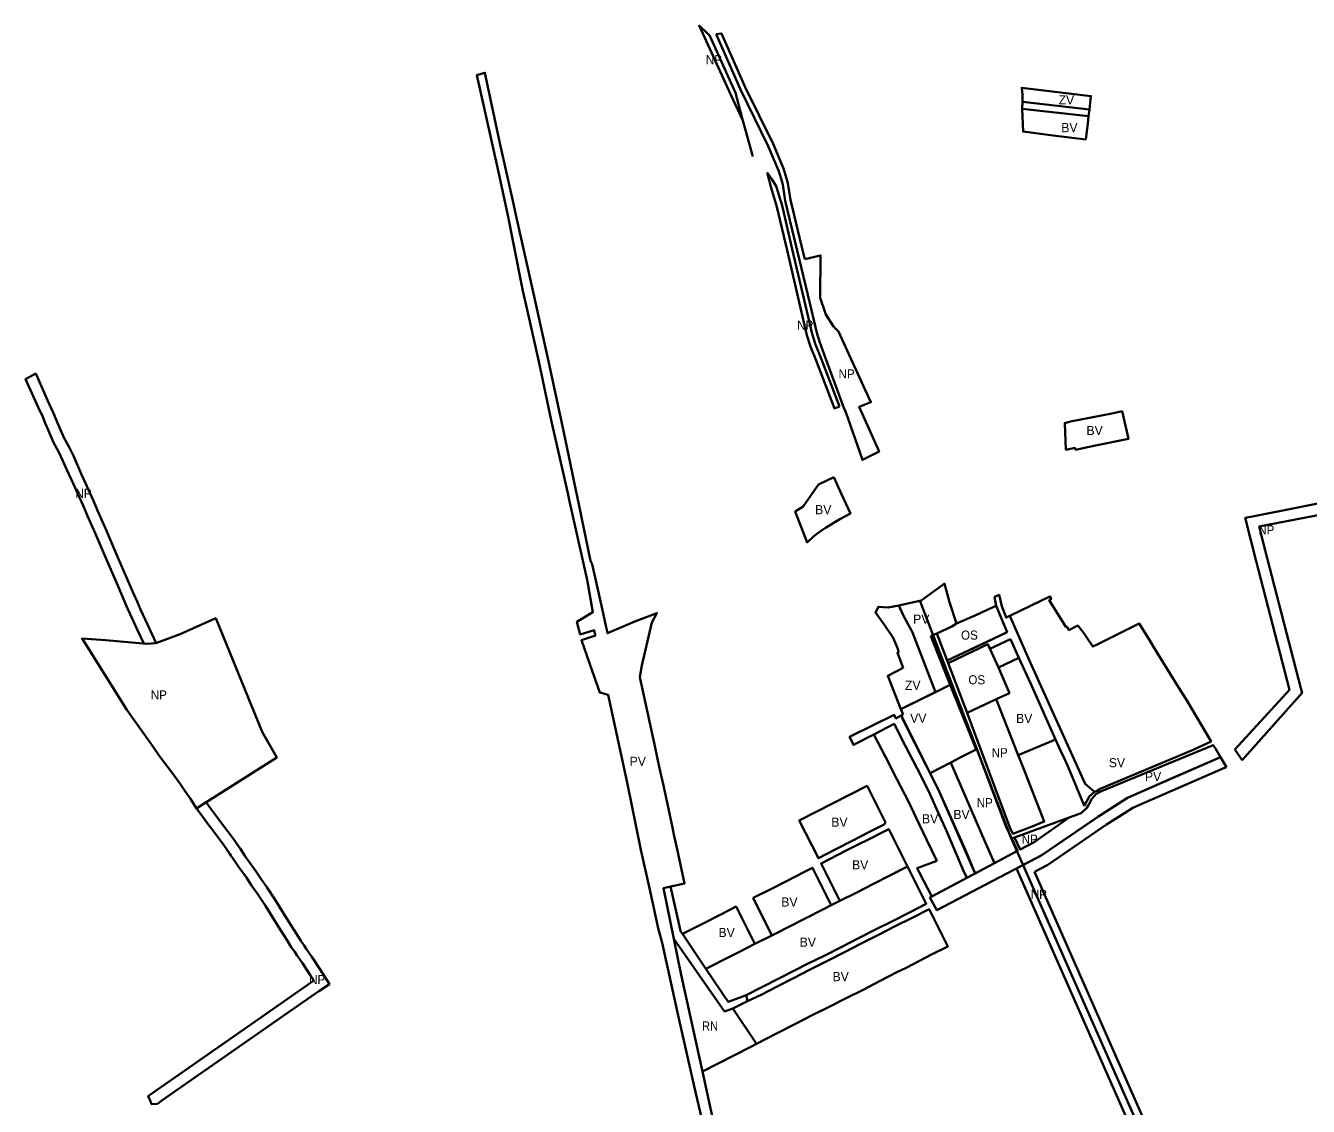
# Model space of a CAD drawing. Extents: x -650276 to -642489, y -1074311 to -1066658.
# Drawn here: x -649558 to -647873, y -1068079 to -1066658 of the extents above; entities that cross this region are included whole.
import ezdxf

# ---------------------------------------------------------------- set-up
doc = ezdxf.new("R2010")
doc.units = 0
doc.header["$LTSCALE"] = 4.8
for name, color, linetype, lineweight in [('15', 7, 'Continuous', 35), ('18', 7, 'Continuous', 35), ('3', 7, 'Continuous', 35), ('40', 7, 'Continuous', 35), ('45', 7, 'Continuous', 35), ('48', 7, 'Continuous', 35), ('54', 7, 'Continuous', 35), ('7', 7, 'Continuous', 35), ('9', 7, 'Continuous', 35)]:
    doc.layers.add(name, color=color, linetype=linetype, lineweight=lineweight)
doc.layers.add('62', color=7, linetype='Continuous')

msp = doc.modelspace()

# ---------------------------------------------------------------- linework, layer by layer
at = {"layer": '15'}
for points in [[(-648662.71, -1068124.76), (-648677.61, -1068061.74), (-648700.16, -1067963.42), (-648722.09, -1067863.84), (-648727.05, -1067844.33), (-648738.7, -1067792.04), (-648749.97, -1067741.49), (-648767.84, -1067652.98), (-648791.68, -1067543.78), (-648792.97, -1067537.86), (-648804.08, -1067534.88), (-648813.94, -1067506.27), (-648827.86, -1067465.86), (-648809.65, -1067459.77), (-648809.97, -1067458.52), (-648811.21, -1067453.52), (-648811.4, -1067452.79), (-648829.54, -1067458.42), (-648834.01, -1067441.81), (-648812.91, -1067429.16), (-648820.39, -1067386.83), (-648844.16, -1067281.37), (-648845.94, -1067272.85), (-648867.82, -1067176.66), (-648884.26, -1067099.63), (-648899.1, -1067033.34), (-648905.06, -1067006.7), (-648917.76, -1066942.65), (-648924.32, -1066909.55), (-648936.7, -1066852.52), (-648944.75, -1066815.41), (-648955.15, -1066770.11), (-648965.39, -1066723.15), (-648959.88, -1066721.59), (-648954.86, -1066720.16), (-648935.19, -1066812.53), (-648918.27, -1066888.41), (-648914.11, -1066907.05), (-648893.02, -1067002.5), (-648872.31, -1067095.5), (-648851.87, -1067191.04), (-648835.29, -1067268.93), (-648833.66, -1067276.77), (-648816.06, -1067361.71), (-648813.81, -1067365.91), (-648799.58, -1067430.4), (-648796.8, -1067443.1), (-648795.88, -1067447.21), (-648794.7, -1067452.46), (-648793.71, -1067456.88), (-648757.97, -1067441.51), (-648728.95, -1067430.33), (-648735.59, -1067442.88), (-648748.53, -1067499.3), (-648751.29, -1067514.57), (-648731.06, -1067607.06), (-648725.8, -1067632.36), (-648720.1, -1067657.12), (-648708.26, -1067712.07), (-648706.08, -1067723.56), (-648702.33, -1067740.84), (-648692.53, -1067785.79), (-648704.614, -1067788.491), (-648710.961, -1067789.906), (-648720.34, -1067792), (-648696.93, -1067905.76), (-648672.31, -1068017.25), (-648668.92, -1068032.96), (-648651.89, -1068111.95)], [(-648710.961, -1067789.906), (-648720.34, -1067792), (-648706.687, -1067858.345), (-648640, -1067954)], [(-648695.27, -1067852.04), (-648697.7, -1067848.43), (-648699.621, -1067840.06), (-648699.593, -1067840.046), (-648710.96, -1067789.91)], [(-648611.61, -1067932.63), (-648620.658, -1067935.93), (-648635.249, -1067941.252), (-648664.41, -1067897.91), (-648695.27, -1067852.04)], [(-648640, -1067954), (-648629.22, -1067950.214), (-648609.91, -1067940.58), (-648611.61, -1067932.63)]]:
    msp.add_lwpolyline(points, dxfattribs=at)
for points in [[(-648161.58, -1066777.41), (-648160.51, -1066768.4), (-648248.43, -1066758.34), (-648248.77, -1066767.43)], [(-648369.01, -1067460.52), (-648361, -1067457.36), (-648341.15, -1067448.14), (-648335.38, -1067444.07), (-648344.41, -1067416.04), (-648349.67, -1067396.88), (-648351.06, -1067391.62), (-648352.16, -1067392.42), (-648353.35, -1067393.29), (-648381.48, -1067413.68), (-648410.92, -1067420.63), (-648409.61, -1067423.44), (-648404.29, -1067434.9), (-648394.92, -1067452.23), (-648393.17, -1067455.88), (-648362.585, -1067534.205), (-648343.41, -1067524.81), (-648369.01, -1067460.52)], [(-648237.81, -1067522.42), (-648204.88, -1067596.54), (-648198.39, -1067610.97), (-648193.8, -1067621), (-648189.03, -1067631.71), (-648167.48, -1067683.45), (-648164.79, -1067678.96), (-648163.11, -1067676.17), (-648160.68, -1067671.55), (-648153.98, -1067665.43), (-648166.173, -1067654.853), (-648240.51, -1067489.9), (-648265.197, -1067434.03), (-648265.197, -1067434.03), (-648270.02, -1067436.37), (-648275.41, -1067421.3), (-648279.24, -1067406.38), (-648285.08, -1067409.24), (-648283.21, -1067420.88), (-648268.67, -1067455.43), (-648297.915, -1067469.319), (-648326.09, -1067482.7), (-648347.51, -1067492.87), (-648346.27, -1067496.14), (-648294.04, -1067471.35), (-648291.172, -1067477.571), (-648264.34, -1067464.83), (-648253.1, -1067489.23)], [(-648359.6, -1067691.58), (-648348.55, -1067716.71), (-648337.32, -1067742.59), (-648326, -1067769), (-648321.623, -1067778.399), (-648310.511, -1067772.476), (-648323.178, -1067741.953), (-648359.213, -1067661.956), (-648405.054, -1067571.837), (-648408.002, -1067565.219), (-648414.73, -1067568.8), (-648417.19, -1067564.02), (-648475.78, -1067593.11), (-648473.34, -1067598.06), (-648470.57, -1067603.69), (-648470.47, -1067603.64), (-648443.83, -1067589.92), (-648417.12, -1067576.17), (-648402.02, -1067605.49), (-648386.91, -1067634.83), (-648371.34, -1067665.08)], [(-647988.235, -1067619.912), (-647995.04, -1067608.56), (-647997.68, -1067604.11), (-648144.83, -1067664.48), (-648151.6, -1067668.12), (-648157.2, -1067674.32), (-648161, -1067680.96), (-648162.69, -1067684), (-648164.09, -1067686.51), (-648171.21, -1067693.37), (-648187.139, -1067699.179), (-648233.264, -1067731.288), (-648251.711, -1067741.124), (-648258.96, -1067725.37), (-648262.632, -1067726.711), (-648255.016, -1067742.886), (-648319.983, -1067777.526), (-648370.113, -1067804.22), (-648360.993, -1067821.027), (-648222.872, -1067748.412), (-648146.127, -1067695.8), (-648110.36, -1067673.133), (-647988.052, -1067619.624)]]:
    msp.add_lwpolyline(points, close=True, dxfattribs=at)
at = {"layer": '18'}
msp.add_lwpolyline([(-648153.98, -1067665.43), (-648149.933, -1067663.646), (-648146.21, -1067661.3), (-648023.96, -1067610.13), (-648000.63, -1067599.14), (-648031.77, -1067546.6), (-648045.04, -1067525.15), (-648076.32, -1067474.6), (-648081.31, -1067466.54), (-648095.28, -1067444.06), (-648133.56, -1067463.2), (-648150.46, -1067471.66), (-648155.85, -1067474.35), (-648164.24, -1067462.15), (-648166.97, -1067458.18), (-648170.38, -1067453.23), (-648175.94, -1067446.89), (-648187.44, -1067452.8), (-648190.23, -1067447.83), (-648191.46, -1067448.59), (-648213.34, -1067413.46), (-648210.48, -1067411.68), (-648211.08, -1067410.6), (-648212.32, -1067408.39), (-648224.19, -1067414.14), (-648265.197, -1067434.03), (-648240.51, -1067489.9), (-648240.51, -1067489.9), (-648166.173, -1067654.853)], close=True, dxfattribs=at)
at = {"layer": '3'}
for points in [[(-648165.33, -1066807.74), (-648162.8, -1066786.8), (-648161.58, -1066777.41), (-648248.77, -1066767.43), (-648247.78, -1066797.53), (-648211.58, -1066802.18)], [(-648185.185, -1067178.687), (-648193.02, -1067180.66), (-648191.44, -1067215.62), (-648179.42, -1067213.37), (-648179, -1067215.71), (-648152.5, -1067210.23), (-648109.1, -1067201.21), (-648117.562, -1067165.197), (-648131.01, -1067167.84)], [(-648496.55, -1067251.53), (-648516.47, -1067261.54), (-648536.84, -1067290.29), (-648547.17, -1067296.68), (-648531.51, -1067337.57), (-648523.55, -1067330.33), (-648518.55, -1067326.3), (-648507.25, -1067318.35), (-648488.66, -1067307.11), (-648474.69, -1067299.66), (-648486.79, -1067273.26), (-648492.62, -1067260.53)], [(-648253.1, -1067489.23), (-648279.86, -1067502.11), (-648265.757, -1067535.555), (-648282.863, -1067543.596), (-648254.04, -1067616.96), (-648204.88, -1067596.54), (-648237.81, -1067522.42)], [(-648397.98, -1067678.79), (-648388.526, -1067698.603), (-648373.99, -1067728.95), (-648361.08, -1067755.88), (-648387.04, -1067765.67), (-648384.25, -1067771.07), (-648367.811, -1067802.994), (-648321.623, -1067778.399), (-648326, -1067769), (-648337.32, -1067742.59), (-648348.55, -1067716.71), (-648359.6, -1067691.58), (-648371.34, -1067665.08), (-648386.91, -1067634.83), (-648402.02, -1067605.49), (-648417.12, -1067576.17), (-648443.83, -1067589.92), (-648428.7, -1067619.24), (-648413.57, -1067648.57)], [(-648342.697, -1067626.806), (-648369.949, -1067640.851), (-648359.213, -1067661.956), (-648310.511, -1067772.476), (-648285.254, -1067759.008), (-648296.891, -1067732.172), (-648342.023, -1067628.096)], [(-648519.63, -1067691.58), (-648541.86, -1067702.86), (-648516.73, -1067752.57), (-648494.84, -1067741.06), (-648472.5, -1067729.76), (-648450.23, -1067718.32), (-648430.17, -1067708.33), (-648428.67, -1067705.52), (-648452.72, -1067657.62)], [(-648491.14, -1067748.02), (-648513.23, -1067759.38), (-648488.49, -1067808.76), (-648466.36, -1067797.5), (-648455.32, -1067791.85), (-648444.28, -1067786.19), (-648421.84, -1067774.66), (-648410.78, -1067768.98), (-648399.64, -1067763.26), (-648424.14, -1067714.34), (-648435.34, -1067720.01), (-648446.58, -1067725.71), (-648468.97, -1067736.91), (-648480.06, -1067742.47)], [(-648577.78, -1067854.07), (-648571.69, -1067851.06), (-648555.32, -1067842.99), (-648532.98, -1067831.54), (-648510.82, -1067820.19), (-648499.7, -1067814.37), (-648524.44, -1067765.11), (-648535.61, -1067770.85), (-648557.84, -1067782.26), (-648580.14, -1067793.61), (-648602.3, -1067804.83)], [(-648644.095, -1067887.6), (-648620.51, -1067875.63), (-648600.14, -1067865.29), (-648624.76, -1067816.11), (-648645.11, -1067826.48), (-648668.085, -1067838.186), (-648675.26, -1067841.84), (-648695.27, -1067852.04), (-648664.41, -1067897.91), (-648650.68, -1067890.94)]]:
    msp.add_lwpolyline(points, close=True, dxfattribs=at)
for points in [[(-648611.61, -1067932.63), (-648611.61, -1067932.63), (-648547.09, -1067899.87), (-648530.81, -1067891.61), (-648508.22, -1067880.38), (-648486.09, -1067868.98), (-648463.91, -1067857.74), (-648441.47, -1067846.37), (-648419.44, -1067835.3), (-648397.04, -1067823.85), (-648374.84, -1067812.43), (-648399.64, -1067763.26), (-648421.84, -1067774.66)], [(-648421.84, -1067774.66), (-648444.28, -1067786.19), (-648455.32, -1067791.85), (-648466.36, -1067797.5), (-648488.49, -1067808.76)], [(-648488.49, -1067808.76), (-648499.7, -1067814.37), (-648510.82, -1067820.19), (-648532.98, -1067831.54), (-648555.32, -1067842.99), (-648571.69, -1067851.06)], [(-648572.5, -1067983.59), (-648546.76, -1067970.44), (-648524.72, -1067958.93), (-648502.59, -1067948), (-648480.12, -1067936.55), (-648457.87, -1067925.4), (-648435.55, -1067913.84), (-648413.41, -1067902.53), (-648402.29, -1067897.02), (-648391.08, -1067891.24), (-648368.78, -1067879.75), (-648346.57, -1067868.56), (-648371.27, -1067819.47), (-648393.35, -1067830.81), (-648415.69, -1067841.98), (-648426.65, -1067847.64), (-648437.89, -1067853.4), (-648460.33, -1067864.88), (-648482.5, -1067876.22), (-648504.92, -1067887.52), (-648527.33, -1067898.74), (-648549.44, -1067910.07), (-648571.88, -1067921.71), (-648591.04, -1067931.62), (-648609.91, -1067940.58)], [(-648600.14, -1067865.29), (-648620.51, -1067875.63), (-648644.095, -1067887.6)], [(-648571.69, -1067851.06), (-648577.78, -1067854.07), (-648600.14, -1067865.29)], [(-648644.095, -1067887.6), (-648650.68, -1067890.94), (-648664.41, -1067897.91), (-648635.249, -1067941.252), (-648620.658, -1067935.93), (-648611.61, -1067932.63)], [(-648609.91, -1067940.58), (-648629.22, -1067950.214), (-648597.93, -1067996.72), (-648572.5, -1067983.59)]]:
    msp.add_lwpolyline(points, dxfattribs=at)
at = {"layer": '40'}
for points in [[(-648160.51, -1066768.4), (-648159.66, -1066759.8), (-648158.49, -1066750.93), (-648249.44, -1066739.8), (-648248.34, -1066749.33), (-648248.43, -1066758.34)], [(-648405.27, -1067502.27), (-648425.5, -1067512.73), (-648408.26, -1067556.58), (-648362.585, -1067534.205), (-648393.17, -1067455.88), (-648394.92, -1067452.23), (-648404.29, -1067434.9), (-648410.92, -1067420.63), (-648425, -1067423.05), (-648437.75, -1067421.99), (-648441.48, -1067429.63), (-648430.4, -1067445.51), (-648418.3, -1067462.86), (-648412.46, -1067477.42), (-648411.25, -1067481.73), (-648412.89, -1067482.55)]]:
    msp.add_lwpolyline(points, close=True, dxfattribs=at)
at = {"layer": '45'}
msp.add_lwpolyline([(-648405.41, -1067563.84), (-648408.002, -1067565.219), (-648369.949, -1067640.851), (-648342.697, -1067626.806), (-648328.54, -1067619.51), (-648309.522, -1067609.713), (-648317.43, -1067590), (-648343.41, -1067524.81), (-648408.26, -1067556.58)], close=True, dxfattribs=at)
at = {"layer": '48'}
for points in [[(-648602.97, -1066830.11), (-648616.86, -1066779.79), (-648625.44, -1066746.45), (-648659.95, -1066670.89), (-648662.46, -1066668.53), (-648673.407, -1066658.275), (-648631.791, -1066749.394)], [(-648534.701, -1066965.077), (-648538.812, -1066947.891), (-648553.323, -1066887.238), (-648556.637, -1066865.397), (-648559.94, -1066854.66), (-648562.542, -1066846.219), (-648576.145, -1066813.802), (-648612.763, -1066739.165), (-648643.925, -1066668.483), (-648651.042, -1066669.551), (-648651.1, -1066669.56)], [(-648651.1, -1066669.56), (-648619.11, -1066742.12), (-648582.52, -1066816.7)], [(-648631.791, -1066749.394), (-648616.104, -1066782.727), (-648602.97, -1066830.11)], [(-648582.52, -1066816.7), (-648569.13, -1066848.61), (-648566.63, -1066856.72), (-648563.48, -1066866.96), (-648560.2, -1066888.58), (-648541.521, -1066966.657), (-648541.52, -1066966.657)], [(-648571.96, -1066869.37), (-648577.99, -1066860.17), (-648583.94, -1066851.11)], [(-648583.94, -1066851.11), (-648578.702, -1066871.259), (-648571.167, -1066896.326), (-648557.816, -1066953.444)], [(-648489.1, -1067158.84), (-648512.95, -1067095.97), (-648520.4, -1067077.42), (-648524.93, -1067063.35), (-648533.66, -1067026), (-648551, -1066951.85), (-648564.4, -1066894.52), (-648571.96, -1066869.37)], [(-648557.816, -1066953.444), (-648540.476, -1067027.594), (-648531.681, -1067065.222)], [(-648541.52, -1066966.657), (-648528.01, -1067023.13), (-648518.72, -1067061.99), (-648514.86, -1067074.83), (-648507.88, -1067093.9), (-648483.31, -1067160.63), (-648480.57, -1067166.13), (-648458.73, -1067229.1), (-648449.03, -1067224.14), (-648437.02, -1067217.99), (-648462.97, -1067159.24), (-648447.66, -1067153.25), (-648467.56, -1067110.02), (-648490.23, -1067060.06), (-648496.87, -1067053.5), (-648506.78, -1067037.81), (-648514.38, -1067016.2), (-648513.842, -1066960.243), (-648534.701, -1066965.077)], [(-648531.681, -1067065.222), (-648526.988, -1067079.8), (-648519.471, -1067098.516), (-648495.644, -1067161.326), (-648489.1, -1067158.84)], [(-647882.66, -1067529.231), (-647926.759, -1067358.379), (-647937.355, -1067316.774), (-647828.376, -1067295.406), (-647828.104, -1067295.352), (-647831.28, -1067280.69), (-647948.488, -1067303.671)], [(-647948.488, -1067303.671), (-647955.805, -1067305.106), (-647941.289, -1067362.104)], [(-647941.289, -1067362.104), (-647897.637, -1067531.223), (-647969.29, -1067609.79), (-647959.832, -1067623.65)], [(-648265.08, -1067712.06), (-648261.25, -1067720.39), (-648235.78, -1067710.79), (-648219.86, -1067704.42), (-648247.53, -1067633.53), (-648254.04, -1067616.96), (-648282.863, -1067543.596), (-648321.36, -1067561.69)], [(-647959.832, -1067623.65), (-647881.085, -1067535.333), (-647882.66, -1067529.231)], [(-648321.361, -1067561.69), (-648311.95, -1067586.45), (-648265.08, -1067712.06)], [(-647980.561, -1067632.719), (-647982.95, -1067628.73), (-647988.334, -1067619.747), (-648046.773, -1067645.314)], [(-648046.773, -1067645.314), (-648110.36, -1067673.133), (-648146.127, -1067695.8), (-648146.146, -1067695.813), (-648149.529, -1067698.132), (-648222.53, -1067748.178)], [(-648095.475, -1067682.994), (-647983.06, -1067633.813), (-647980.561, -1067632.719)], [(-648232.676, -1067770.513), (-648215.115, -1067761.28), (-648137.869, -1067708.325), (-648114.323, -1067693.403), (-648103.298, -1067686.416), (-648095.475, -1067682.994)], [(-648222.53, -1067748.178), (-648222.872, -1067748.412), (-648238.748, -1067756.759)], [(-648238.748, -1067756.759), (-648256.499, -1067766.091), (-648079.002, -1068168.139)], [(-648079.002, -1068168.139), (-648061.329, -1068158.649), (-648232.676, -1067770.513)]]:
    msp.add_lwpolyline(points, dxfattribs=at)
for points in [[(-649545.203, -1067115.647), (-649549.7, -1067118.05), (-649558.469, -1067122.73), (-649541.537, -1067160.722), (-649536.075, -1067172.622), (-649532.831, -1067180.855), (-649529.013, -1067189.389), (-649521.663, -1067206.124), (-649514.869, -1067218.957), (-649509.44, -1067230.141), (-649504.224, -1067242.225), (-649498.572, -1067254.427), (-649493.526, -1067265.611), (-649487.812, -1067278.312), (-649482.963, -1067288.934), (-649477.677, -1067301.655), (-649472.327, -1067313.644), (-649466.703, -1067326.24), (-649451.059, -1067363.074), (-649439.265, -1067390.397), (-649430.531, -1067410.689), (-649425.804, -1067421.21), (-649421.071, -1067431.944), (-649411.913, -1067451.746), (-649403.34, -1067470.579), (-649399.39, -1067470.93), (-649387.4, -1067469.98), (-649387.17, -1067469.894), (-649398.28, -1067445.49), (-649407.4, -1067425.77), (-649412.1, -1067415.11), (-649416.8, -1067404.65), (-649425.49, -1067384.46), (-649437.27, -1067357.17), (-649452.95, -1067320.25), (-649458.63, -1067307.53), (-649463.9, -1067295.72), (-649469.21, -1067282.94), (-649474.15, -1067272.12), (-649479.85, -1067259.45), (-649484.93, -1067248.19), (-649490.53, -1067236.1), (-649495.8, -1067223.89), (-649501.49, -1067212.17), (-649508.15, -1067199.59), (-649515.3, -1067183.31), (-649519, -1067175.04), (-649522.27, -1067166.74), (-649527.87, -1067154.54)], [(-649333.74, -1067687.4), (-649335.26, -1067685.21), (-649341.81, -1067674.33), (-649349.12, -1067663.84), (-649355.46, -1067654.85), (-649364.69, -1067641.98), (-649382.53, -1067618.33), (-649391.04, -1067606.27), (-649393.23, -1067603.28), (-649425.69, -1067557.7), (-649484.28, -1067463.88), (-649453.39, -1067466.13), (-649399.39, -1067470.93), (-649387.4, -1067469.98), (-649355.44, -1067457.94), (-649329.068, -1067446.175), (-649308.75, -1067437.11), (-649247.518, -1067586.255), (-649228.52, -1067620.294), (-649320.47, -1067678.44)], [(-648342.023, -1067628.096), (-648296.891, -1067732.172), (-648285.254, -1067759.008), (-648255.016, -1067742.886), (-648265.614, -1067720.378), (-648269.27, -1067712.6), (-648308.43, -1067609.15), (-648328.54, -1067619.51), (-648342.697, -1067626.806)], [(-649321.3, -1067679), (-649333.74, -1067687.4), (-649328.34, -1067694.79), (-649317.99, -1067708.85), (-649312.91, -1067715.45), (-649298.02, -1067735.58), (-649290.15, -1067746.92), (-649288.63, -1067748.97), (-649282.85, -1067757.79), (-649278.14, -1067764.31), (-649268.46, -1067777.97), (-649261.48, -1067788.47), (-649253.98, -1067799.2), (-649243.37, -1067815.17), (-649241.28, -1067818.7), (-649228.27, -1067839.26), (-649222.11, -1067849.12), (-649215.32, -1067859.99), (-649209.39, -1067869.34), (-649204.87, -1067875.85), (-649202.02, -1067880.07), (-649194.77, -1067890.67), (-649184, -1067906.88), (-649179.96, -1067913.35), (-649219.088, -1067940.964), (-649395.729, -1068064.23), (-649397.466, -1068065.442), (-649394.83, -1068071.05), (-649392.88, -1068075.9), (-649385.41, -1068075.32), (-649379.295, -1068071.053), (-649210.54, -1067953.29), (-649172.99, -1067927.41), (-649159.179, -1067918.309), (-649171.389, -1067898.756), (-649182.332, -1067882.285), (-649189.614, -1067871.638), (-649192.493, -1067867.375), (-649196.89, -1067861.042), (-649202.625, -1067852), (-649209.388, -1067841.173), (-649215.571, -1067831.276), (-649228.486, -1067810.867), (-649230.661, -1067807.193), (-649241.584, -1067790.752), (-649249.085, -1067780.02), (-649256.092, -1067769.48), (-649265.941, -1067755.582), (-649270.491, -1067749.283), (-649276.322, -1067740.385), (-649277.961, -1067738.175), (-649285.826, -1067726.842), (-649300.936, -1067706.414), (-649306.005, -1067699.828), (-649316.244, -1067685.919)], [(-648258.96, -1067725.37), (-648251.711, -1067741.124), (-648233.264, -1067731.288), (-648187.139, -1067699.179)]]:
    msp.add_lwpolyline(points, close=True, dxfattribs=at)
at = {"layer": '54'}
msp.add_lwpolyline([(-648383.36, -1067413.938), (-648264.607, -1067722.965), (-648014.937, -1068288.491)], dxfattribs=at)
at = {"layer": '7'}
msp.add_lwpolyline([(-648640, -1067954), (-648706.687, -1067858.345), (-648696.93, -1067905.76), (-648668.92, -1068032.96), (-648605.323, -1068000.463), (-648597.93, -1067996.72), (-648629.22, -1067950.214)], close=True, dxfattribs=at)
at = {"layer": '9'}
for points in [[(-648268.67, -1067455.43), (-648283.21, -1067420.88), (-648295.66, -1067426.76), (-648309.57, -1067433.34), (-648335.38, -1067444.07), (-648341.15, -1067448.14), (-648361, -1067457.36), (-648347.51, -1067492.87), (-648326.09, -1067482.7)], [(-648334.09, -1067528.2), (-648321.36, -1067561.69), (-648282.863, -1067543.596), (-648265.757, -1067535.555), (-648279.86, -1067502.11), (-648294.04, -1067471.35), (-648346.27, -1067496.14)]]:
    msp.add_lwpolyline(points, close=True, dxfattribs=at)

# ---------------------------------------------------------------- texts
at = {"layer": '62'}
for s, width, p in [('NP', 0.95, (-648664.583, -1066709.041)), ('NP', 0.95, (-648544.583, -1067058.041)), ('NP', 0.95, (-648490.15, -1067121.972)), ('NP', 0.95, (-649492.985, -1067278.967)), ('NP', 0.95, (-647938.583, -1067327.041)), ('OS', 0.95, (-648329.213, -1067465.317)), ('OS', 0.95, (-648319.549, -1067524.064)), ('NP', 0.95, (-649393.985, -1067543.967)), ('NP', 0.95, (-648289.019, -1067619.94)), ('NP', 0.95, (-648308.631, -1067685.579)), ('NP', 0.95, (-648249.631, -1067733.579)), ('NP', 0.95, (-648237.583, -1067806.041)), ('NP', 0.95, (-649185.985, -1067917.967)), ('RN', 0.9, (-648669.473, -1067979.058))]:
    msp.add_text(s, height=12, dxfattribs=dict(at, width=width)).set_placement(p)
for s, p in [('ZV', (-648201.026, -1066761.906)), ('BV', (-648197.475, -1066798.284)), ('BV', (-648164.386, -1067196.331)), ('BV', (-648520.956, -1067300.498)), ('PV', (-648392.213, -1067444.317)), ('ZV', (-648402.918, -1067531.307)), ('VV', (-648396.075, -1067574.614)), ('BV', (-648256.942, -1067574.923)), ('PV', (-648764.767, -1067631.209)), ('SV', (-648135.028, -1067633.035)), ('PV', (-648087.517, -1067651.275)), ('BV', (-648380.551, -1067706.775)), ('BV', (-648339.301, -1067701.063)), ('BV', (-648499.724, -1067711.153)), ('BV', (-648472.48, -1067767.243)), ('BV', (-648565.429, -1067816.121)), ('BV', (-648647.961, -1067856.185)), ('BV', (-648541.281, -1067868.87)), ('BV', (-648498.112, -1067914.191))]:
    msp.add_text(s, height=12, dxfattribs=at).set_placement(p)

doc.saveas('drawing.dxf')
